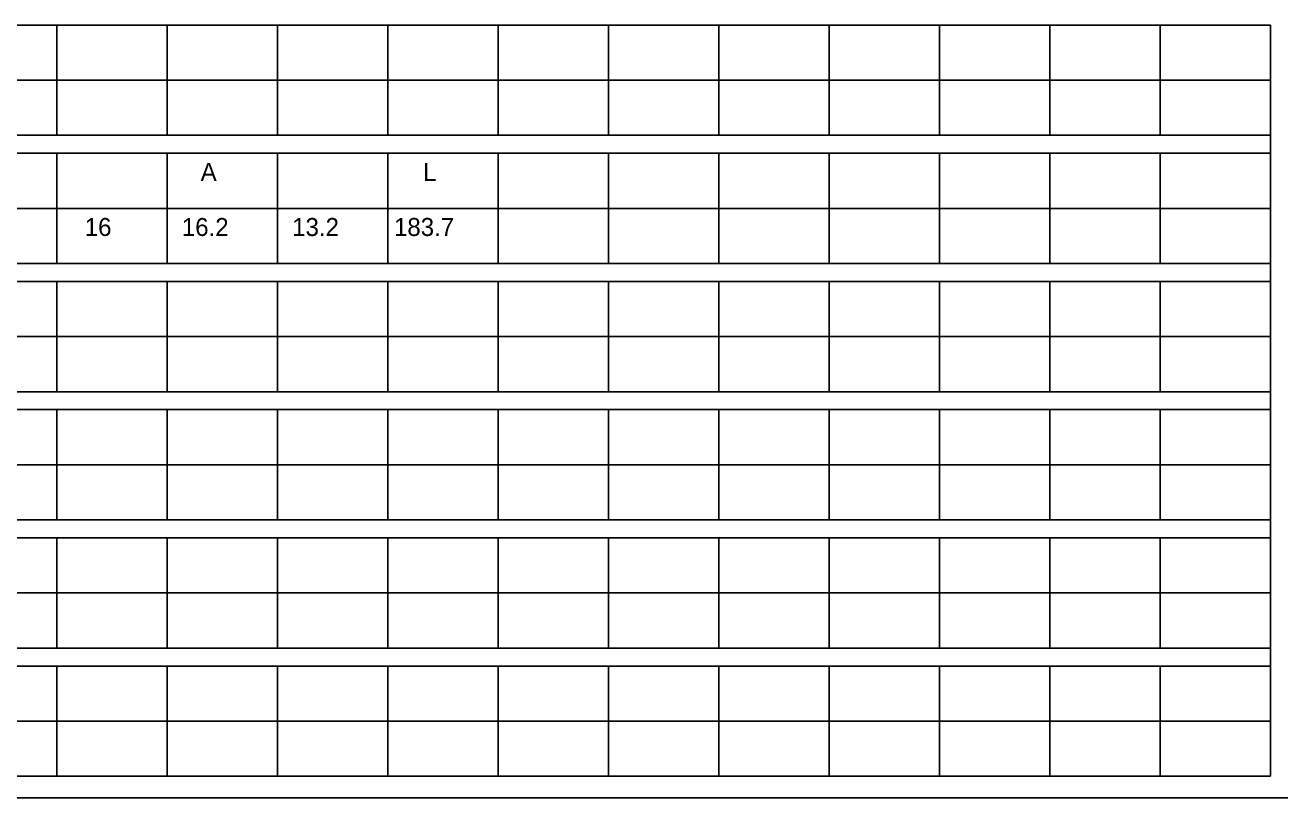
# Model space of a CAD drawing. Extents: x 122633 to 124574, y -23288 to -22025.
# Drawn here: x 123189.8 to 123600.6, y -22601.1 to -22348.2 of the extents above; entities that cross this region are included whole.
import ezdxf

# ---------------------------------------------------------------- set-up
doc = ezdxf.new("R2010")
doc.units = 0
doc.layers.add('GSSign', color=7, linetype='Continuous')
doc.layers.add('SheetLinesMisc2_dp', color=7, linetype='Continuous')

msp = doc.modelspace()

# ---------------------------------------------------------------- linework, layer by layer
at = {"layer": 'SheetLinesMisc2_dp'}
for p, q in [((122709.67, -22348.2), (123597.5, -22348.2)), ((123200.22, -22348.2), (123200.22, -22384.27)), ((123236.33, -22348.2), (123236.33, -22384.27)), ((123272.46, -22348.2), (123272.46, -22384.27)), ((123308.57, -22348.2), (123308.57, -22384.27)), ((123344.68, -22348.2), (123344.68, -22384.27)), ((123380.8, -22348.2), (123380.8, -22384.27)), ((123416.92, -22348.2), (123416.92, -22384.27)), ((123453.04, -22348.2), (123453.04, -22384.27)), ((123489.15, -22348.2), (123489.15, -22384.27)), ((123525.26, -22348.2), (123525.26, -22384.27)), ((123561.39, -22348.2), (123561.39, -22384.27)), ((123597.5, -22594.02), (123597.5, -22348.2)), ((122709.67, -22366.23), (123597.5, -22366.23)), ((122709.67, -22384.27), (123597.5, -22384.27)), ((122709.67, -22390.15), (123597.5, -22390.15)), ((123200.22, -22390.15), (123200.22, -22426.22)), ((123236.33, -22390.15), (123236.33, -22426.22)), ((123272.46, -22390.15), (123272.46, -22426.22)), ((123308.57, -22390.15), (123308.57, -22426.22)), ((123344.68, -22390.15), (123344.68, -22426.22)), ((123380.8, -22390.15), (123380.8, -22426.22)), ((123416.92, -22390.15), (123416.92, -22426.22)), ((123453.04, -22390.15), (123453.04, -22426.22)), ((123489.15, -22390.15), (123489.15, -22426.22)), ((123525.26, -22390.15), (123525.26, -22426.22)), ((123561.39, -22390.15), (123561.39, -22426.22)), ((122709.67, -22408.19), (123597.5, -22408.18)), ((122709.67, -22426.22), (123597.5, -22426.22)), ((122709.67, -22432.1), (123597.5, -22432.1)), ((123200.22, -22432.1), (123200.22, -22468.17)), ((123236.33, -22432.1), (123236.33, -22468.17)), ((123272.46, -22432.1), (123272.46, -22468.17)), ((123308.57, -22432.1), (123308.57, -22468.17)), ((123344.68, -22432.1), (123344.68, -22468.17)), ((123380.8, -22432.1), (123380.8, -22468.17)), ((123416.92, -22432.1), (123416.92, -22468.17)), ((123453.04, -22432.1), (123453.04, -22468.17)), ((123489.15, -22432.1), (123489.15, -22468.17)), ((123525.26, -22432.1), (123525.26, -22468.17)), ((123561.39, -22432.1), (123561.39, -22468.17)), ((122709.67, -22450.14), (123597.5, -22450.14)), ((122709.67, -22468.17), (123597.5, -22468.17)), ((122709.67, -22474.05), (123597.5, -22474.05)), ((123200.22, -22474.05), (123200.22, -22510.12)), ((123236.33, -22474.05), (123236.33, -22510.12)), ((123272.46, -22474.05), (123272.46, -22510.12)), ((123308.57, -22474.05), (123308.57, -22510.12)), ((123344.68, -22474.05), (123344.68, -22510.12)), ((123380.8, -22474.05), (123380.8, -22510.12)), ((123416.92, -22474.05), (123416.92, -22510.12)), ((123453.04, -22474.05), (123453.04, -22510.12)), ((123489.15, -22474.05), (123489.15, -22510.12)), ((123525.26, -22474.05), (123525.26, -22510.12)), ((123561.39, -22474.05), (123561.39, -22510.12)), ((122709.67, -22492.09), (123597.5, -22492.09)), ((122709.67, -22510.12), (123597.5, -22510.12)), ((122709.67, -22516.01), (123597.5, -22516.01)), ((123200.22, -22516.01), (123200.22, -22552.08)), ((123236.33, -22516.01), (123236.33, -22552.08)), ((123272.46, -22516.01), (123272.46, -22552.08)), ((123308.57, -22516.01), (123308.57, -22552.08)), ((123344.68, -22516.01), (123344.68, -22552.08)), ((123380.8, -22516.01), (123380.8, -22552.08)), ((123416.92, -22516.01), (123416.92, -22552.08)), ((123453.04, -22516.01), (123453.04, -22552.08)), ((123489.15, -22516.01), (123489.15, -22552.08)), ((123525.26, -22516.01), (123525.26, -22552.08)), ((123561.39, -22516.01), (123561.39, -22552.08)), ((122709.67, -22534.04), (123597.5, -22534.04)), ((122709.67, -22552.08), (123597.5, -22552.08)), ((122709.67, -22557.96), (123597.5, -22557.96)), ((123200.22, -22557.96), (123200.22, -22594.02)), ((123236.33, -22557.96), (123236.33, -22594.02)), ((123272.46, -22557.96), (123272.46, -22594.02)), ((123308.57, -22557.96), (123308.57, -22594.02)), ((123344.68, -22557.96), (123344.68, -22594.02)), ((123380.8, -22557.96), (123380.8, -22594.02)), ((123416.92, -22557.96), (123416.92, -22594.02)), ((123453.04, -22557.96), (123453.04, -22594.02)), ((123489.15, -22557.96), (123489.15, -22594.02)), ((123525.26, -22557.96), (123525.26, -22594.02)), ((123561.39, -22557.96), (123561.39, -22594.02)), ((122709.67, -22575.98), (123597.5, -22575.98)), ((122709.67, -22594.02), (123597.5, -22594.02)), ((122701.01, -22601.11), (124506.26, -22601.11))]:
    msp.add_line(p, q, dxfattribs=at)

# ---------------------------------------------------------------- texts
at = {"layer": 'GSSign'}
for s, height, p in [('A', 5.88, (123247.29, -22399.17)), ('L', 5.88, (123320.1, -22399.17)), ('16', 5.882, (123209.35, -22417.21)), ('16.2', 5.882, (123241.13, -22417.21)), ('13.2', 5.882, (123277.25, -22417.21)), ('183.7', 5.882, (123310.58, -22417.21))]:
    msp.add_text(s, height=height, dxfattribs=at).set_placement(p)

doc.saveas('drawing.dxf')
